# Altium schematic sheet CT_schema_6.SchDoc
size 411 x 401 mm
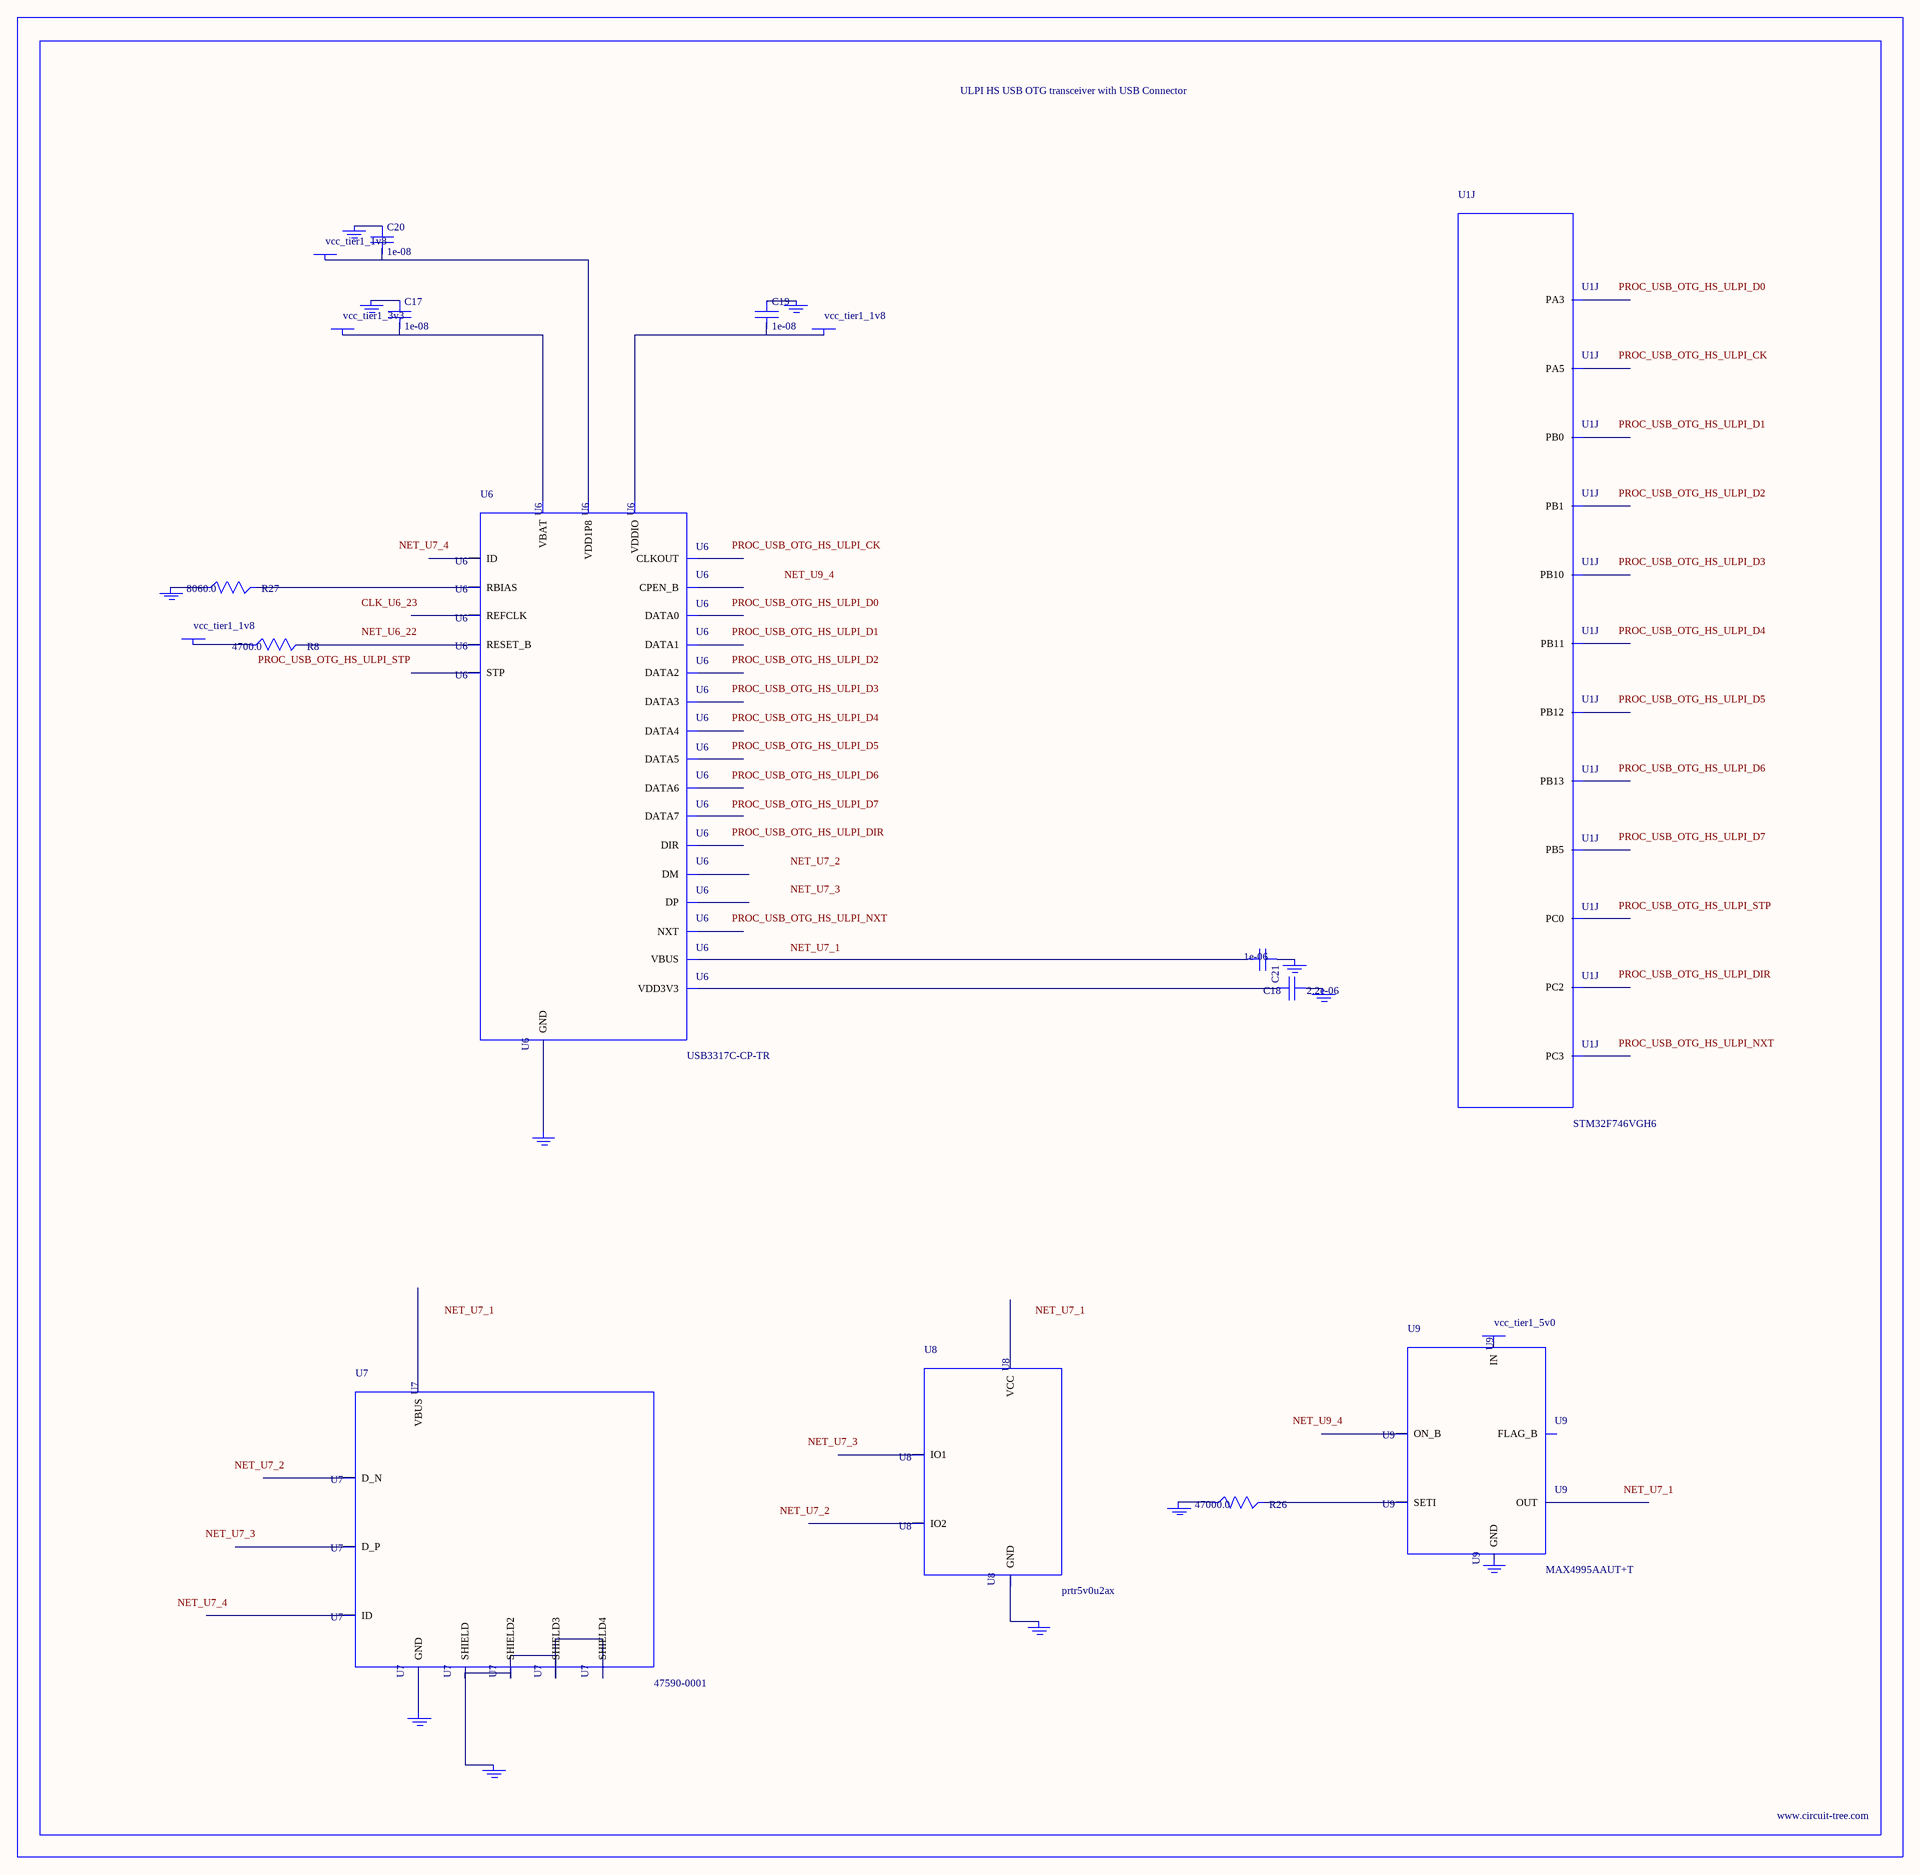
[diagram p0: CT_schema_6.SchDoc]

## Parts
BORDER5  (no value)
C17  1e-08  [C0402]
C18  2.2e-06  [C0603]
C19  1e-08  [C0402]
C20  1e-08  [C0402]
C21  1e-06  [C0603]
GND_INSTANCE_5_0  (no value)
GND_INSTANCE_5_1  (no value)
GND_INSTANCE_5_2  (no value)
GND_INSTANCE_5_3  (no value)
GND_INSTANCE_5_4  (no value)
GND_INSTANCE_5_5  (no value)
GND_INSTANCE_5_6  (no value)
GND_INSTANCE_5_7  (no value)
GND_INSTANCE_5_8  (no value)
GND_INSTANCE_5_9  (no value)
GND_INSTANCE_5_10  (no value)
GND_INSTANCE_5_11  (no value)
POWER_INSTANCE_5_0  vcc_tier1_3v3
POWER_INSTANCE_5_1  vcc_tier1_1v8
POWER_INSTANCE_5_2  vcc_tier1_1v8
POWER_INSTANCE_5_3  vcc_tier1_1v8
POWER_INSTANCE_5_4  vcc_tier1_5v0
R8  4700.0  [R0603]
R26  47000.0  [R0603]
R27  8060.0  [R0603]
U1  STM32F746VGH6  [TFBGA100]  (part J of 10)
U6  USB3317C-CP-TR  [QFN-24]
U7  47590-0001  [MICRO_USB_AB]
U8  prtr5v0u2ax  [SOT143B]
U9  MAX4995AAUT+T  [SOT-23-6]

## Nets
NetC17_1: C17.1 GND_INSTANCE_5_1.0(GND)
NetC17_2: C17.2 POWER_INSTANCE_5_0.0(PWR) U6.3(VBAT)
NetC18_1: C18.1 GND_INSTANCE_5_2.0(GND)
NetC18_2: C18.2 U6.4(VDD3V3)
NetC19_1: C19.1 GND_INSTANCE_5_3.0(GND)
NetC19_2: C19.2 POWER_INSTANCE_5_1.0(PWR) U6.17(VDDIO)
NetC20_1: C20.1 GND_INSTANCE_5_4.0(GND)
NetC20_2: C20.2 POWER_INSTANCE_5_2.0(PWR) U6.21(VDD1P8)
NetC21_1: C21.1 GND_INSTANCE_5_0.0(GND)
NetC21_2: C21.2 U6.2(VBUS)
NetGND_INSTANCE_5_5_0: GND_INSTANCE_5_5.0(GND) R27.1
NetGND_INSTANCE_5_6_0: GND_INSTANCE_5_6.0(GND) U6.25(GND)
NetGND_INSTANCE_5_7_0: GND_INSTANCE_5_7.0(GND) U7.6(SHIELD) U7.7(SHIELD2) U7.8(SHIELD3) U7.9(SHIELD4)
NetGND_INSTANCE_5_8_0: GND_INSTANCE_5_8.0(GND) U7.5(GND)
NetGND_INSTANCE_5_9_0: GND_INSTANCE_5_9.0(GND) U8.1(GND)
NetGND_INSTANCE_5_10_0: GND_INSTANCE_5_10.0(GND) R26.1
NetPOWER_INSTANCE_5_3_0: POWER_INSTANCE_5_3.0(PWR) R8.1
NetR8_2: R8.2 U6.22(RESET_B)
NetR26_2: R26.2 U9.3(SETI)
NetR27_2: R27.2 U6.24(RBIAS)

Not connected (* = marked no-connect by the designer): GND_INSTANCE_5_11 0(GND); POWER_INSTANCE_5_4 0(PWR); U1 C5(PB5) E2(PC2) F1(PC0) F3(PC3) H3(PA5) J4(PB0) J7(PB10) J8(PB13) K2(PA3) K4(PB1) K7(PB11) K8(PB12); U6 1(ID) 5(DM) 6(DP) 7(CPEN_B) 8(DATA7) 9(DATA6) 10(DATA5) 11(DATA4) 12(CLKOUT) 13(DATA3) 14(DATA2) 15(DATA1) 16(DATA0) 18(NXT) 19(DIR) 20(STP) 23(REFCLK); U7 1(VBUS) 2(D_N) 3(D_P) 4(ID); U8 2(IO1) 3(IO2) 4(VCC); U9 1(OUT) 2(GND) 4(ON_B) 5(IN) 6(FLAG_B)

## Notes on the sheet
- Labels drawn without touching a wire or pin: CLK_U6_23, NET_U6_22, NET_U7_1, NET_U7_2, NET_U7_3, NET_U7_4, NET_U9_4, PROC_USB_OTG_HS_ULPI_CK, PROC_USB_OTG_HS_ULPI_D0, PROC_USB_OTG_HS_ULPI_D1, PROC_USB_OTG_HS_ULPI_D2, PROC_USB_OTG_HS_ULPI_D3, PROC_USB_OTG_HS_ULPI_D4, PROC_USB_OTG_HS_ULPI_D5, PROC_USB_OTG_HS_ULPI_D6, PROC_USB_OTG_HS_ULPI_D7, PROC_USB_OTG_HS_ULPI_DIR, PROC_USB_OTG_HS_ULPI_NXT, PROC_USB_OTG_HS_ULPI_STP

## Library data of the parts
BORDER5 = BORDER_PAGE5
C17 C19 C20 = C0402C103K3RAC
C18 = C0603C225K8RACTU
C21 = C0603C105K3RACTU
GND_INSTANCE_5_0-GND_INSTANCE_5_11 = GND
POWER_INSTANCE_5_0-POWER_INSTANCE_5_4 = PWR
R8 = RC0603JR-074K7L
R26 = RC0603JR-0747KL
R27 = ERJ-3EKF8061V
